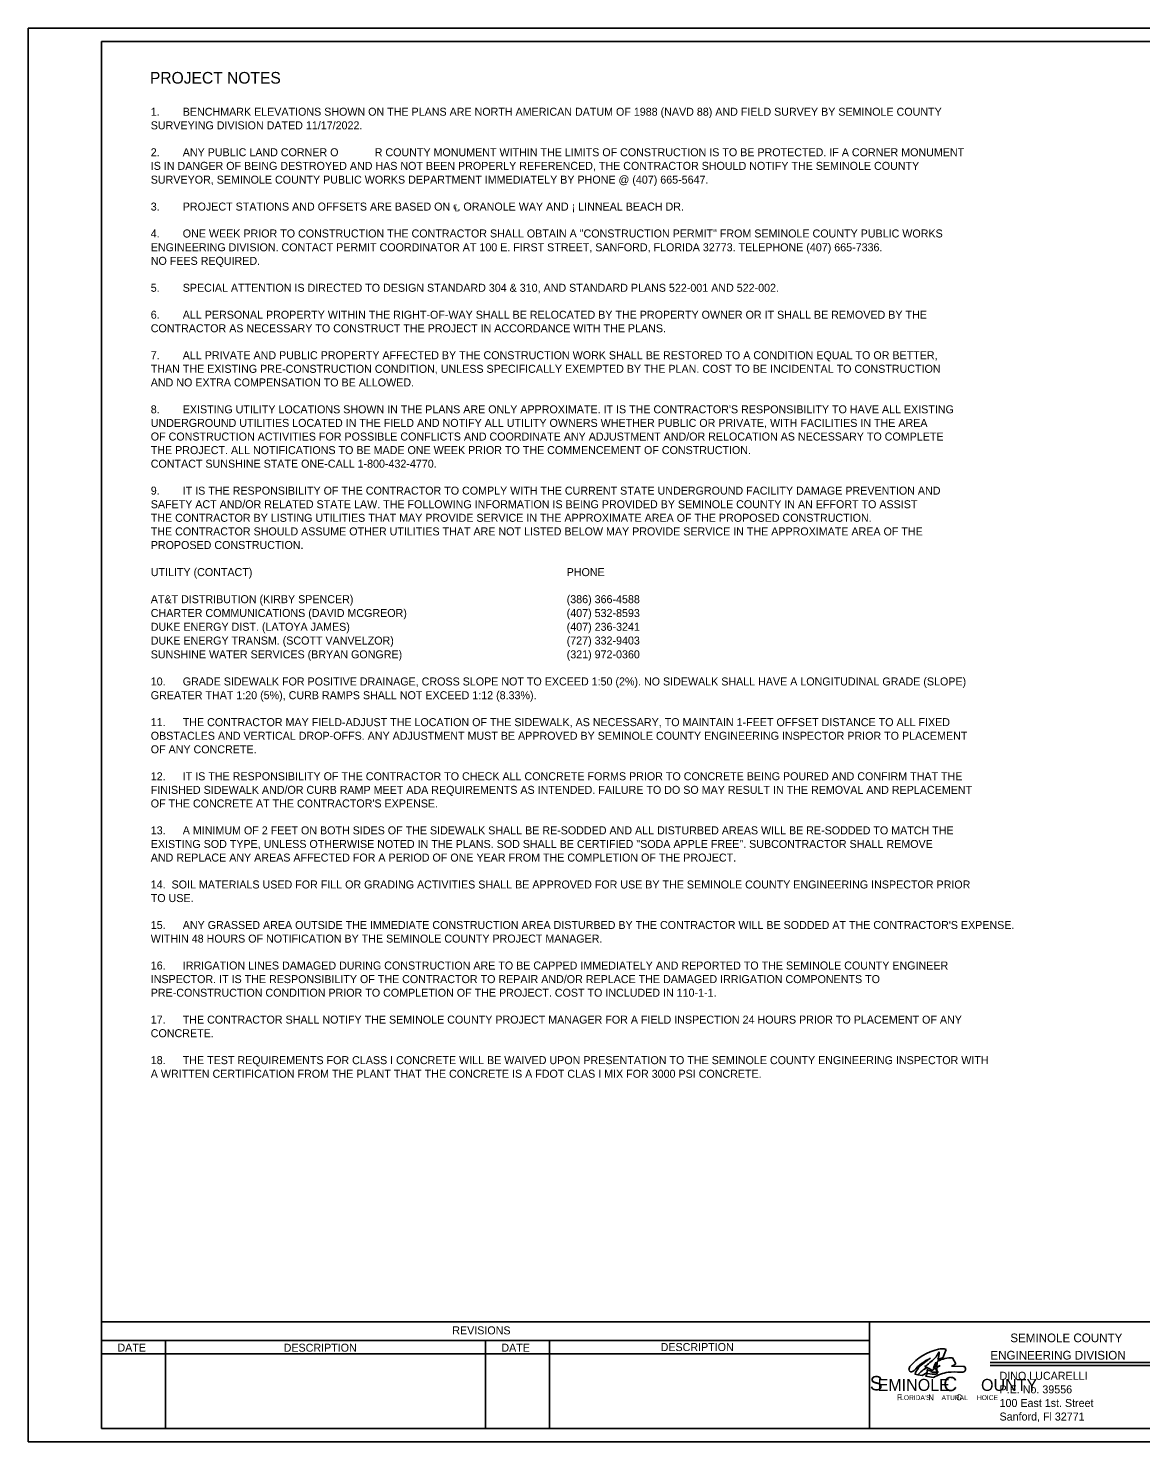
# Model space of a CAD drawing. Extents: x 9949 to 10609, y 9645 to 10069.
# Drawn here: x 9948.8 to 10282.6, y 9645.5 to 10069.5 of the extents above; entities that cross this region are included whole.
import ezdxf

# ---------------------------------------------------------------- set-up
doc = ezdxf.new("R2010")
doc.units = 0
for name, color, linetype in [('AdhocPoint_dp', 7, 'Continuous'), ('Default', 7, 'Continuous'), ('Logo_dp', 7, 'Continuous'), ('PlotBorder_dp', 7, 'Continuous'), ('ScratchEle_dp', 7, 'Continuous'), ('SheetBorder_dp', 7, 'Continuous'), ('SheetLines_dp', 7, 'Continuous'), ('TextMisc', 7, 'Continuous')]:
    doc.layers.add(name, color=color, linetype=linetype)

msp = doc.modelspace()

# ---------------------------------------------------------------- linework, layer by layer
at = {"layer": 'AdhocPoint_dp'}
msp.add_line((9948.8, 9645.47), (9948.8, 9645.47), dxfattribs=at)
at = {"layer": 'Logo_dp'}
for p, q in [((10223.21, 9670.6), (10224.23, 9673.17)), ((10229.34, 9668.08), (10225.79, 9668.16)), ((10227.11, 9668.79), (10226.15, 9670.63)), ((10215.7, 9665.55), (10217.05, 9665.29)), ((10217.05, 9665.29), (10218.53, 9666.28)), ((10217.97, 9665.12), (10220.38, 9664.78)), ((10218.53, 9666.28), (10218.53, 9666.86)), ((10219.21, 9666.71), (10219.77, 9667.07)), ((10221.77, 9666.58), (10221.27, 9665.78))]:
    msp.add_line(p, q, dxfattribs=at)
for points in [[(10221.86, 9673.2), (10221.86, 9673.2)], [(10215.94, 9667.59), (10215.94, 9667.59)]]:
    msp.add_lwpolyline(points, dxfattribs=at)
for centre, radius, start, end in [((10225.43, 9657.72), 15.89, 102.9903, 139.6059), ((10215.74, 9675.46), 7.05, 315.4846, 334.5843), ((10213.15, 9672.67), 8.96, 343.2724, 358.4983), ((10222.98, 9668.37), 4.96, 75.3253, 102.9903), ((10214.26, 9667.23), 1.22, 139.6059, 196.4516), ((10225.63, 9657.36), 14.53, 114.9659, 139.5324), ((10219.31, 9664.4), 4.64, 136.5671, 163.5792), ((10222.84, 9659.24), 9.53, 117.2749, 138.5612), ((10222.84, 9659.24), 9.53, 117.2749, 138.5612), ((10229.61, 9654.64), 18.84, 122.4911, 136.5671), ((10205.94, 9685.1), 20.79, 304.6341, 315.4846), ((10216.72, 9664.2), 3.93, 63.4009, 74.6531), ((10212.43, 9654.04), 14.96, 60.5981, 66.1485), ((10234.35, 9644.92), 26.24, 120.5054, 124.3665), ((10227.1, 9665.81), 6.91, 149.8559, 166.6084), ((10226.49, 9655.99), 12.96, 115.0847, 118.1751), ((10225.15, 9668.19), 4.17, 164.7271, 186.2913), ((10222.55, 9667.73), 1.54, 187.6078, 223.6575), ((10233.96, 9667.13), 12.58, 177.2074, 179.7242), ((10234.35, 9644.92), 26.24, 117.0216, 119.5789), ((10233.96, 9667.13), 12.58, 168.5397, 176.4368), ((10226.49, 9655.99), 12.96, 108.2919, 113.1245), ((10225.95, 9660.9), 9.74, 88.8097, 116.3253), ((10224.83, 9663.43), 7.35, 102.6743, 114.927), ((10224.37, 9672.81), 4.86, 286.9862, 304.2368), ((10229.37, 9667.44), 0.643, 0.9885, 92.5741), ((10228.95, 9667.35), 1.07, 319.3898, 5.6197), ((10213.66, 9667.05), 0.599, 196.4516, 259.2243), ((10213.76, 9667.57), 1.12, 259.2243, 316.3038), ((10211.74, 9647.09), 18.88, 77.906, 80.5112), ((10228.89, 9656.36), 13.99, 136.6419, 141.2542), ((10217.93, 9666.76), 0.608, 9.3089, 39.4038), ((10218.12, 9666.03), 1.15, 52.8844, 76.2699), ((10220.59, 9673.83), 8.09, 256.604, 274.8219), ((10220.01, 9668.46), 1.93, 231.8585, 245.4301), ((10220.65, 9668.72), 2.41, 242.5498, 297.6527), ((10227.66, 9650.89), 15.68, 100.5294, 117.6775), ((10223.09, 9667.12), 1.71, 177.7479, 195.3391), ((10226.69, 9645.36), 21.03, 84.8254, 95.1746), ((10228.78, 9667.83), 1.53, 262.9671, 309.9257)]:
    msp.add_arc(centre, radius, start, end, dxfattribs=at)
at = {"layer": 'PlotBorder_dp'}
msp.add_lwpolyline([(9948.8, 9645.47), (10608.8, 9645.47), (10608.8, 10069.47), (9948.8, 10069.47)], close=True, dxfattribs=at)
at = {"layer": 'SheetBorder_dp'}
for p, q in [((9970.8, 10065.47), (9970.8, 9649.47)), ((9970.8, 10065.47), (10586.8, 10065.47)), ((9970.8, 9681.47), (10586.8, 9681.47)), ((9970.8, 9649.47), (10586.8, 9649.47))]:
    msp.add_line(p, q, dxfattribs=at)
at = {"layer": 'SheetLines_dp'}
for p, q in [((10201.2, 9681.47), (10201.2, 9649.47)), ((9970.8, 9675.87), (10201.2, 9675.87)), ((9990, 9675.87), (9990, 9649.47)), ((10086, 9675.87), (10086, 9649.47)), ((10105.2, 9675.87), (10105.2, 9649.47)), ((9970.8, 9671.87), (10201.2, 9671.87))]:
    msp.add_line(p, q, dxfattribs=at)
at = {"layer": 'TextMisc'}
for p, q in [((10237.36, 9668.35), (10292.82, 9668.35)), ((10237.44, 9669.25), (10292.9, 9669.25))]:
    msp.add_line(p, q, dxfattribs=at)

# ---------------------------------------------------------------- texts
at = {"layer": 'Default'}
msp.add_text('PROJECT NOTES', height=3.5, dxfattribs=at).set_placement((9985.3, 10052.86))
at = {"layer": 'Logo_dp'}
for s, height, p in [('S', 4.32, (10201.3, 9660.87)), ('EMINOLE       OUNTY', 3.6, (10203.64, 9660.71)), ('C', 4.32, (10223.36, 9660.64)), ('F', 1.8, (10209.45, 9657.87)), ("LORIDA'S      ATURAL     HOICE", 1.44, (10210.41, 9657.97)), ('N', 1.8, (10218.82, 9657.87)), ('C', 1.8, (10227.19, 9657.87))]:
    msp.add_text(s, height=height, dxfattribs=at).set_placement(p)
at = {"layer": 'ScratchEle_dp'}
for s, height, p in [('Sheet: 1', 0.118, (9970.8, 9681.57)), ('Angle:  90.0153', 0.1181, (9970.8, 9681.41)), ('Align: CH269', 0.1181, (9970.8, 9681.25))]:
    msp.add_text(s, height=height, dxfattribs=at).set_placement(p)
at = {"layer": 'TextMisc'}
for s, height, p in [('1.', 2.4, (9985.55, 10043.23)), ('BENCHMARK ELEVATIONS SHOWN ON THE PLANS ARE NORTH AMERICAN DATUM OF 1988 (NAVD 88) AND FIELD SURVEY BY SEMINOLE COUNTY ', 2.4, (9995.15, 10043.23)), ('SURVEYING DIVISION DATED 11/17/2022.', 2.4, (9985.55, 10039.15)), ('2.', 2.4, (9985.55, 10031.07)), ('ANY PUBLIC LAND CORNER O', 2.4, (9995.15, 10031.07)), ('R COUNTY MONUMENT WITHIN THE LIMITS OF CONSTRUCTION IS TO BE PROTECTED. IF A CORNER MONUMENT ', 2.4, (10052.75, 10031.07)), ('IS IN DANGER OF BEING DESTROYED AND HAS NOT BEEN PROPERLY REFERENCED, THE CONTRACTOR SHOULD NOTIFY THE SEMINOLE COUNTY', 2.4, (9985.55, 10026.99)), ('SURVEYOR, SEMINOLE COUNTY PUBLIC WORKS DEPARTMENT IMMEDIATELY BY PHONE @ (407) 665-5647.', 2.4, (9985.55, 10022.86)), ('3.', 2.4, (9985.55, 10014.78)), ('PROJECT STATIONS AND OFFSETS ARE BASED ON ℄. ORANOLE WAY AND ¡ LINNEAL BEACH DR.', 2.4, (9995.15, 10014.78)), ('4.', 2.4, (9985.55, 10006.71)), ('ONE WEEK PRIOR TO CONSTRUCTION THE CONTRACTOR SHALL OBTAIN A "CONSTRUCTION PERMIT" FROM SEMINOLE COUNTY PUBLIC WORKS', 2.4, (9995.15, 10006.71)), ('ENGINEERING DIVISION. CONTACT PERMIT COORDINATOR AT 100 E. FIRST STREET, SANFORD, FLORIDA 32773. TELEPHONE (407) 665-7336. ', 2.4, (9985.55, 10002.57)), ('NO FEES REQUIRED.', 2.4, (9985.55, 9998.5)), ('5.', 2.4, (9985.55, 9990.42)), ('SPECIAL ATTENTION IS DIRECTED TO DESIGN STANDARD 304 & 310, AND STANDARD PLANS 522-001 AND 522-002.', 2.4, (9995.15, 9990.42)), ('6.', 2.4, (9985.55, 9982.34)), ('ALL PERSONAL PROPERTY WITHIN THE RIGHT-OF-WAY SHALL BE RELOCATED BY THE PROPERTY OWNER OR IT SHALL BE REMOVED BY THE', 2.4, (9995.15, 9982.34)), ('CONTRACTOR AS NECESSARY TO CONSTRUCT THE PROJECT IN ACCORDANCE WITH THE PLANS.', 2.4, (9985.55, 9978.27)), ('7.', 2.4, (9985.55, 9970.19)), ('ALL PRIVATE AND PUBLIC PROPERTY AFFECTED BY THE CONSTRUCTION WORK SHALL BE RESTORED TO A CONDITION EQUAL TO OR BETTER, ', 2.4, (9995.15, 9970.19)), ('THAN THE EXISTING PRE-CONSTRUCTION CONDITION, UNLESS SPECIFICALLY EXEMPTED BY THE PLAN. COST TO BE INCIDENTAL TO CONSTRUCTION ', 2.4, (9985.55, 9966.11)), ('AND NO EXTRA COMPENSATION TO BE ALLOWED.', 2.4, (9985.55, 9962.03)), ('8.', 2.4, (9985.55, 9953.96)), ("EXISTING UTILITY LOCATIONS SHOWN IN THE PLANS ARE ONLY APPROXIMATE. IT IS THE CONTRACTOR'S RESPONSIBILITY TO HAVE ALL EXISTING", 2.4, (9995.15, 9953.96)), ('UNDERGROUND UTILITIES LOCATED IN THE FIELD AND NOTIFY ALL UTILITY OWNERS WHETHER PUBLIC OR PRIVATE, WITH FACILITIES IN THE AREA', 2.4, (9985.55, 9949.88)), ('OF CONSTRUCTION ACTIVITIES FOR POSSIBLE CONFLICTS AND COORDINATE ANY ADJUSTMENT AND/OR RELOCATION AS NECESSARY TO COMPLETE ', 2.4, (9985.55, 9945.8)), ('THE PROJECT. ALL NOTIFICATIONS TO BE MADE ONE WEEK PRIOR TO THE COMMENCEMENT OF CONSTRUCTION. ', 2.4, (9985.55, 9941.73)), ('CONTACT SUNSHINE STATE ONE-CALL 1-800-432-4770.', 2.4, (9985.55, 9937.65)), ('9.', 2.4, (9985.55, 9929.57)), ('IT IS THE RESPONSIBILITY OF THE CONTRACTOR TO COMPLY WITH THE CURRENT STATE UNDERGROUND FACILITY DAMAGE PREVENTION AND ', 2.4, (9995.15, 9929.57)), ('SAFETY ACT AND/OR RELATED STATE LAW. THE FOLLOWING INFORMATION IS BEING PROVIDED BY SEMINOLE COUNTY IN AN EFFORT TO ASSIST ', 2.4, (9985.55, 9925.49)), ('THE CONTRACTOR BY LISTING UTILITIES THAT MAY PROVIDE SERVICE IN THE APPROXIMATE AREA OF THE PROPOSED CONSTRUCTION. ', 2.4, (9985.55, 9921.42)), ('THE CONTRACTOR SHOULD ASSUME OTHER UTILITIES THAT ARE NOT LISTED BELOW MAY PROVIDE SERVICE IN THE APPROXIMATE AREA OF THE ', 2.4, (9985.55, 9917.34)), ('PROPOSED CONSTRUCTION.', 2.4, (9985.55, 9913.26)), ('UTILITY (CONTACT)', 2.4, (9985.55, 9905.13)), ('PHONE', 2.4, (10110.35, 9905.13)), ('AT&T DISTRIBUTION (KIRBY SPENCER)', 2.4, (9985.55, 9897)), ('(386) 366-4588', 2.4, (10110.35, 9897)), ('CHARTER COMMUNICATIONS (DAVID MCGREOR)', 2.4, (9985.55, 9892.86)), ('(407) 532-8593', 2.4, (10110.35, 9892.86)), ('DUKE ENERGY DIST. (LATOYA JAMES)', 2.4, (9985.55, 9888.73)), ('(407) 236-3241', 2.4, (10110.35, 9888.73)), ('DUKE ENERGY TRANSM. (SCOTT VANVELZOR)', 2.4, (9985.55, 9884.6)), ('(727) 332-9403', 2.4, (10110.35, 9884.6)), ('SUNSHINE WATER SERVICES (BRYAN GONGRE)', 2.4, (9985.55, 9880.46)), ('(321) 972-0360', 2.4, (10110.35, 9880.46)), ('GREATER THAT 1:20 (5%), CURB RAMPS SHALL NOT EXCEED 1:12 (8.33%).', 2.4, (9985.55, 9868.2)), ('10.', 2.4, (9985.55, 9872.33)), ('GRADE SIDEWALK FOR POSITIVE DRAINAGE, CROSS SLOPE NOT TO EXCEED 1:50 (2%). NO SIDEWALK SHALL HAVE A LONGITUDINAL GRADE (SLOPE)', 2.4, (9995.15, 9872.33)), ('11.', 2.4, (9985.55, 9860.12)), ('THE CONTRACTOR MAY FIELD-ADJUST THE LOCATION OF THE SIDEWALK, AS NECESSARY, TO MAINTAIN 1-FEET OFFSET DISTANCE TO ALL FIXED ', 2.4, (9995.15, 9860.12)), ('OBSTACLES AND VERTICAL DROP-OFFS. ANY ADJUSTMENT MUST BE APPROVED BY SEMINOLE COUNTY ENGINEERING INSPECTOR PRIOR TO PLACEMENT', 2.4, (9985.55, 9856.04)), ('OF ANY CONCRETE.', 2.4, (9985.55, 9851.97)), ('12.', 2.4, (9985.55, 9843.89)), ('IT IS THE RESPONSIBILITY OF THE CONTRACTOR TO CHECK ALL CONCRETE FORMS PRIOR TO CONCRETE BEING POURED AND CONFIRM THAT THE', 2.4, (9995.15, 9843.89)), ('FINISHED SIDEWALK AND/OR CURB RAMP MEET ADA REQUIREMENTS AS INTENDED. FAILURE TO DO SO MAY RESULT IN THE REMOVAL AND REPLACEMENT', 2.4, (9985.55, 9839.81)), ("OF THE CONCRETE AT THE CONTRACTOR'S EXPENSE.", 2.4, (9985.55, 9835.73)), ('13. ', 2.4, (9985.55, 9827.66)), ('A MINIMUM OF 2 FEET ON BOTH SIDES OF THE SIDEWALK SHALL BE RE-SODDED AND ALL DISTURBED AREAS WILL BE RE-SODDED TO MATCH THE', 2.4, (9995.15, 9827.66)), ('EXISTING SOD TYPE, UNLESS OTHERWISE NOTED IN THE PLANS. SOD SHALL BE CERTIFIED "SODA APPLE FREE". SUBCONTRACTOR SHALL REMOVE ', 2.4, (9985.55, 9823.58)), ('AND REPLACE ANY AREAS AFFECTED FOR A PERIOD OF ONE YEAR FROM THE COMPLETION OF THE PROJECT.', 2.4, (9985.55, 9819.5)), ('14.  SOIL MATERIALS USED FOR FILL OR GRADING ACTIVITIES SHALL BE APPROVED FOR USE BY THE SEMINOLE COUNTY ENGINEERING INSPECTOR PRIOR', 2.4, (9985.55, 9811.43)), ('TO USE.', 2.4, (9985.55, 9807.35)), ('15.', 2.4, (9985.55, 9799.27)), ("ANY GRASSED AREA OUTSIDE THE IMMEDIATE CONSTRUCTION AREA DISTURBED BY THE CONTRACTOR WILL BE SODDED AT THE CONTRACTOR'S EXPENSE.", 2.4, (9995.15, 9799.27)), ('WITHIN 48 HOURS OF NOTIFICATION BY THE SEMINOLE COUNTY PROJECT MANAGER.', 2.4, (9985.55, 9795.19)), ('16.', 2.4, (9985.55, 9787.12)), ('IRRIGATION LINES DAMAGED DURING CONSTRUCTION ARE TO BE CAPPED IMMEDIATELY AND REPORTED TO THE SEMINOLE COUNTY ENGINEER', 2.4, (9995.15, 9787.12)), ('INSPECTOR. IT IS THE RESPONSIBILITY OF THE CONTRACTOR TO REPAIR AND/OR REPLACE THE DAMAGED IRRIGATION COMPONENTS TO ', 2.4, (9985.55, 9783.04)), ('PRE-CONSTRUCTION CONDITION PRIOR TO COMPLETION OF THE PROJECT. COST TO INCLUDED IN 110-1-1.', 2.4, (9985.55, 9778.96)), ('17.', 2.4, (9985.55, 9770.89)), ('THE CONTRACTOR SHALL NOTIFY THE SEMINOLE COUNTY PROJECT MANAGER FOR A FIELD INSPECTION 24 HOURS PRIOR TO PLACEMENT OF ANY', 2.4, (9995.15, 9770.89)), ('CONCRETE.', 2.4, (9985.55, 9766.81)), ('18.', 2.4, (9985.55, 9758.73)), ('THE TEST REQUIREMENTS FOR CLASS I CONCRETE WILL BE WAIVED UPON PRESENTATION TO THE SEMINOLE COUNTY ENGINEERING INSPECTOR WITH ', 2.4, (9995.15, 9758.73)), ('A WRITTEN CERTIFICATION FROM THE PLANT THAT THE CONCRETE IS A FDOT CLAS I MIX FOR 3000 PSI CONCRETE.', 2.4, (9985.55, 9754.65)), ('SEMINOLE COUNTY', 2.6, (10243.46, 9675.32)), ('ENGINEERING DIVISION', 2.6, (10237.49, 9670.12)), ('DINO LUCARELLI', 2.4, (10240.23, 9664.05)), ('P.E. No. 39556', 2.4, (10240.23, 9659.97)), ('100 East 1st. Street', 2.4, (10240.23, 9655.89)), ('Sanford, Fl 32771', 2.4, (10240.23, 9651.82))]:
    msp.add_text(s, height=height, dxfattribs=at).set_placement(p)
for s, rotation, p in [('REVISIONS', 360, (10076.02, 9677.67)), ('DATE', 359.8693, (9975.55, 9672.51)), ('DESCRIPTION', 0.0498, (10025.43, 9672.46)), ('DATE', 359.8693, (10090.75, 9672.48)), ('DESCRIPTION', 0.0498, (10138.54, 9672.66))]:
    msp.add_text(s, height=2.4, rotation=rotation, dxfattribs=at).set_placement(p)

doc.saveas('drawing.dxf')
